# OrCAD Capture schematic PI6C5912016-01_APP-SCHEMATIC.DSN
size B; title: PI6C5912016-01 Application Schematic; rev: 1.0; note: Diodes Inc. Clock IC Application Engineering
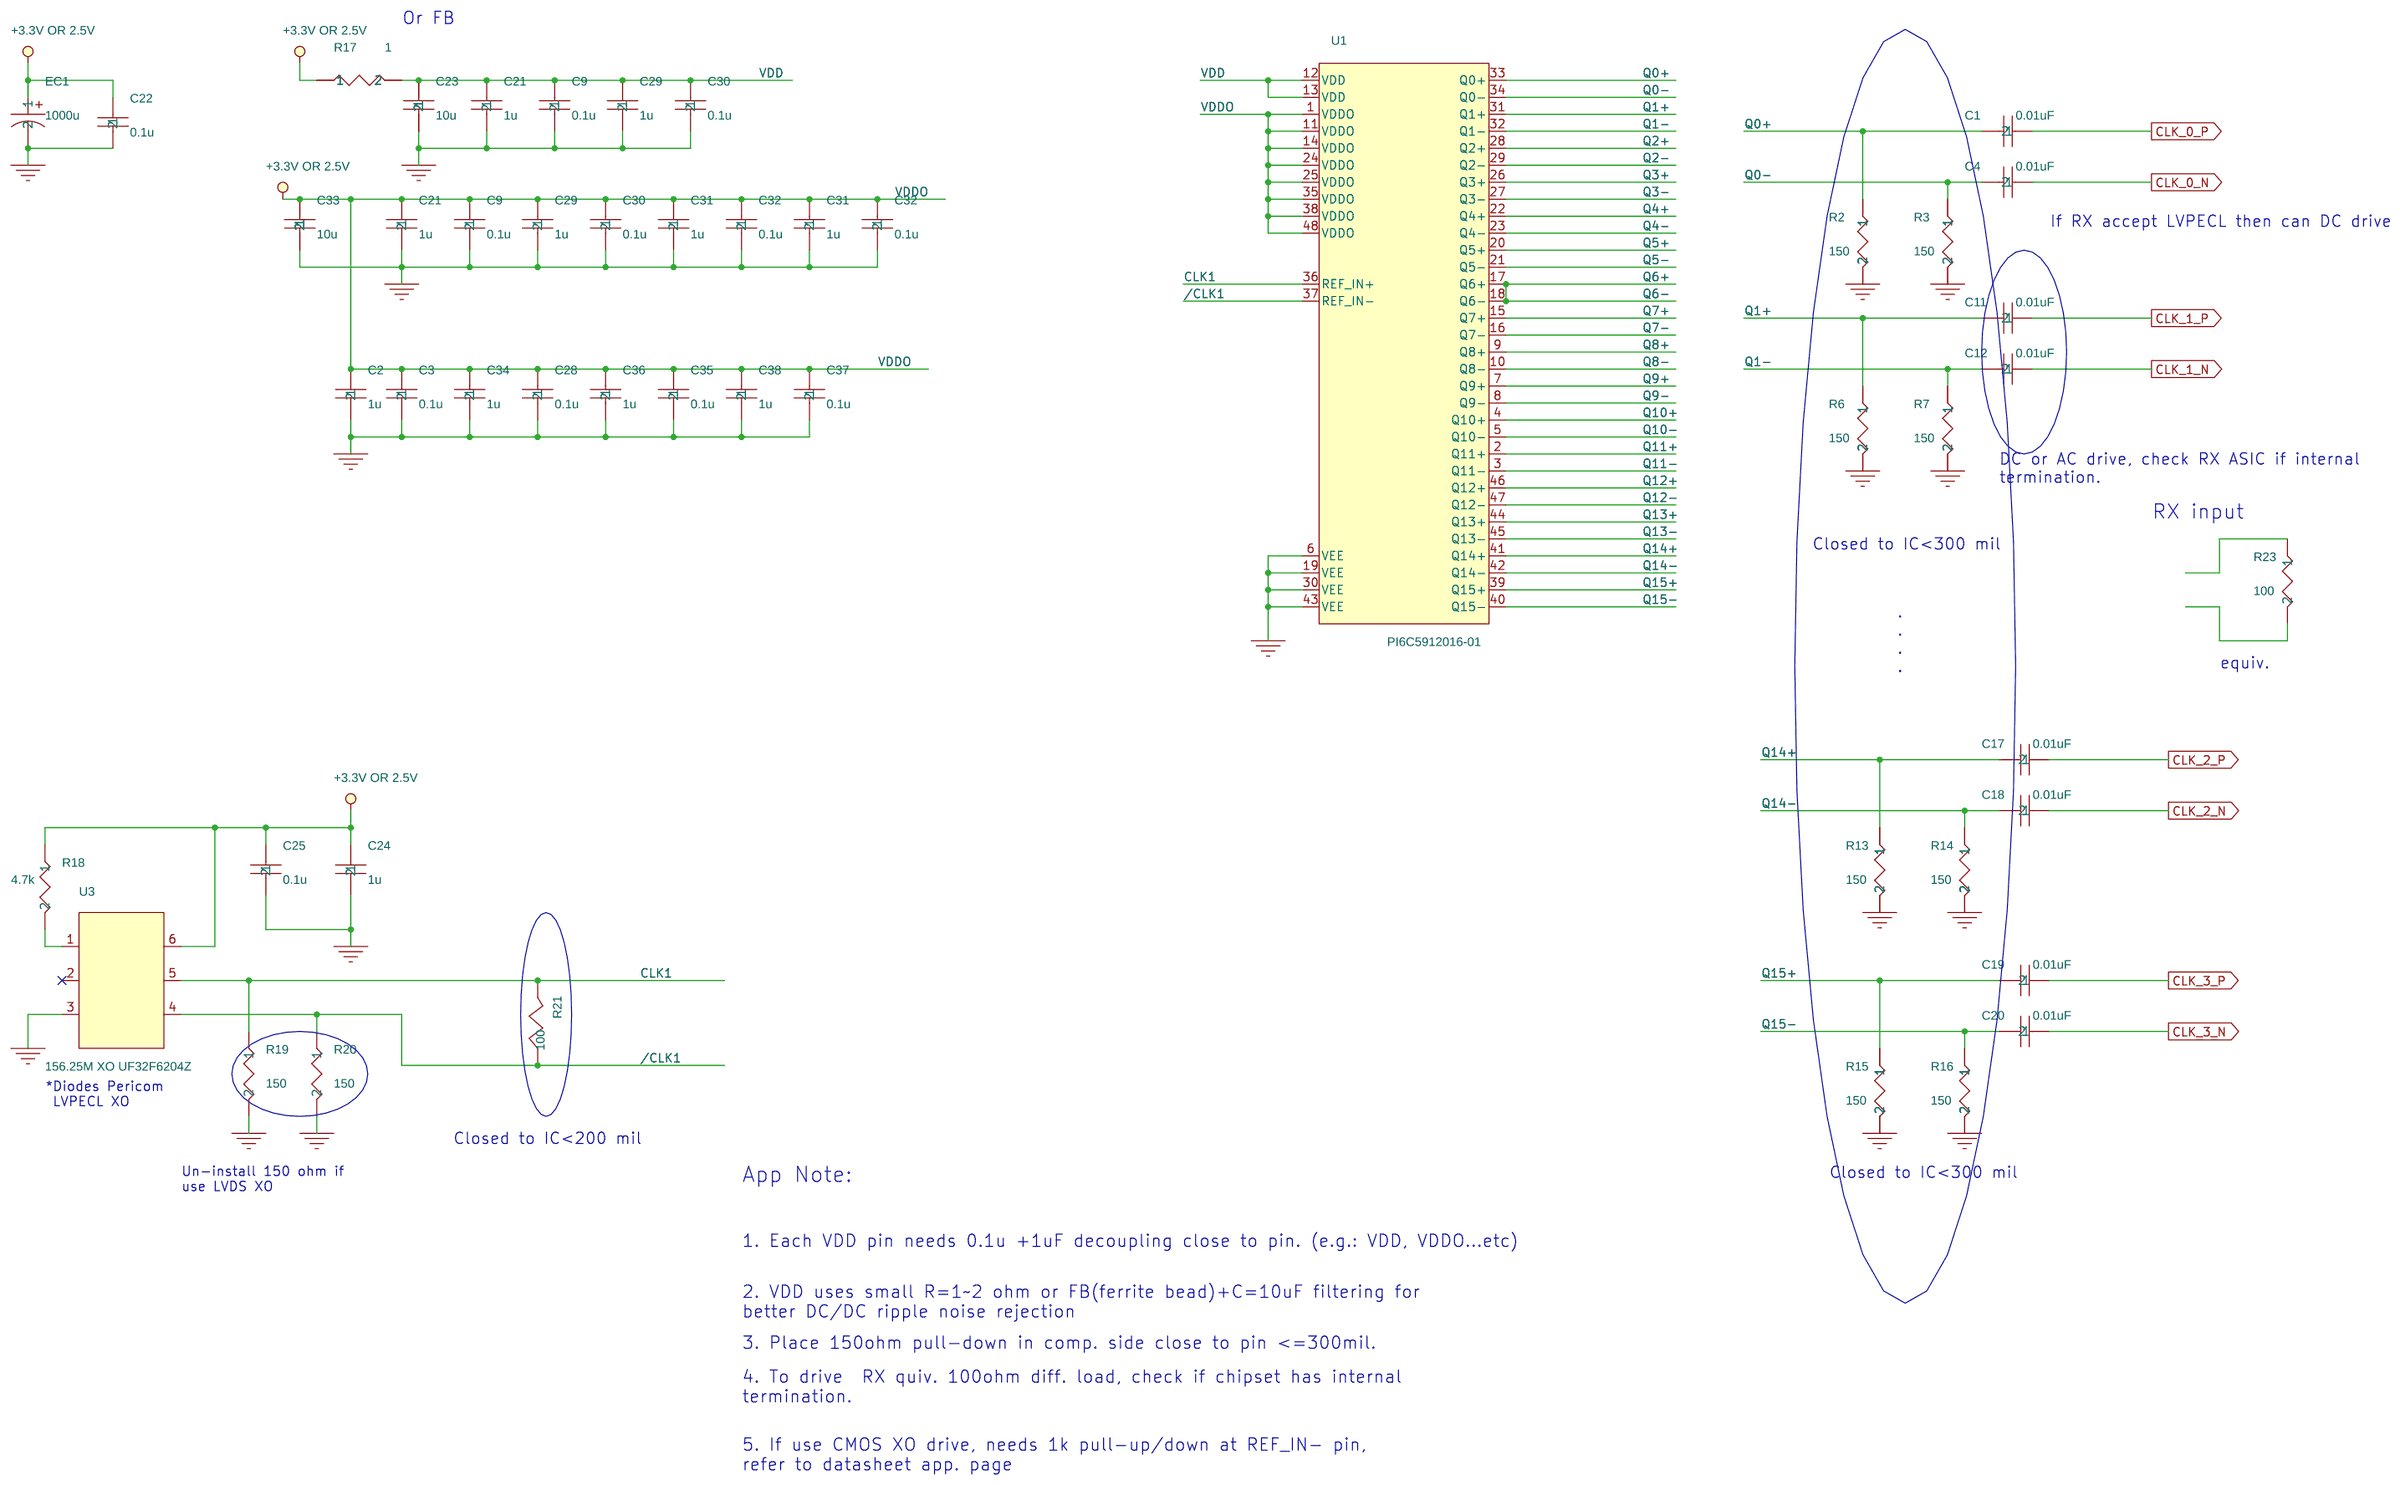
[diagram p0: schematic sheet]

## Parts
C1  0.01uF  [CC_0402]
C2  1u  [CC_0402]
C3  0.1u  [CC_0402]
C4  0.01uF  [CC_0402]
C9  0.1u  [CC_0402]
C9#2  0.1u  [CC_0402]
C11  0.01uF  [CC_0402]
C12  0.01uF  [CC_0402]
C17  0.01uF  [CC_0402]
C18  0.01uF  [CC_0402]
C19  0.01uF  [CC_0402]
C20  0.01uF  [CC_0402]
C21  1u  [CC_0805]
C21#2  1u  [CC_0805]
C22  0.1u  [CC_0402]
C23  10u  [CC_0805]
C24  1u  [CC_0402]
C25  0.1u  [CC_0402]
C28  0.1u  [CC_0402]
C29  1u  [CC_0805]
C29#2  1u  [CC_0805]
C30  0.1u  [CC_0402]
C30#2  0.1u  [CC_0402]
C31  1u  [CC_0805]
C31#2  1u  [CC_0805]
C32  0.1u  [CC_0402]
C32#2  0.1u  [CC_0402]
C33  10u  [CC_0805]
C34  1u  [CC_0402]
C35  0.1u  [CC_0402]
C36  1u  [CC_0402]
C37  0.1u  [CC_0402]
C38  1u  [CC_0402]
EC1  1000u  [CAP1000UF]
R2  150  [R_0402]
R3  150  [R_0402]
R6  150  [R_0402]
R7  150  [R_0402]
R13  150  [R_0402]
R14  150  [R_0402]
R15  150  [R_0402]
R16  150  [R_0402]
R17  1  [R_0402]
R18  4.7k  [R_0402]
R19  150  [R_0402]
R20  150  [R_0402]
R21  100
R23  100  [R_0402]
U1  PI6C5912016-01
U3  156.25M XO UF32F6204Z  [XO 5X7]

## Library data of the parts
C1 = C_10n_0402
C2 = C_0.1u_0402_1
C3 = C_0.1u_0402_8
C4 = C_10n_0402_3
C9 = C_0.1u_0402_12
C9#2 C30#2 C32#2 C38 = C_0.1u_0402
C11 = C_10n_0402_4
C12 = C_10n_0402_2
C17 = C_10n_0402_6
C18 = C_10n_0402_5
C19 = C_10n_0402_7
C20 = C_10n_0402_1
C21 = C_1.0u_0805_4
C21#2 C23 C29#2 C31#2 = C_1.0u_0805
C22 = C_0.1u_0402_6
C24 = C_0.1u_0402_15
C25 = C_0.1u_0402_14
C28 = C_0.1u_0402_9
C29 = C_1.0u_0805_5
C30 = C_0.1u_0402_7
C31 = C_1.0u_0805_7
C32 = C_0.1u_0402_4
C33 = C_1.0u_0805_1
C34 = C_0.1u_0402_5
C35 = C_0.1u_0402_2
C36 = C_0.1u_0402_16
C37 = C_0.1u_0402_3
EC1 = C_alum_1000u
R2 = R_0_2
R3 = R_0_8
R6 = R_0_3
R7 = R_0_7
R13 = R_0_6
R14 = R_0_4
R15 = R_0_5
R16 = R_0
R17 = R_0402
R18 = R_0402_3
R19 = R_0402_2
R20 = R_0402_1
R21 = res1
R23 = R_0_1
U1 = PI6C4911504-03_8
U3 = XO_5X7

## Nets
+3.3V or 2.5V: C2.1 C3.1 C9.1 C21.1 C22.1 C24.1 C25.1 C28.1 C29.1 C30.1 C31.1 C31#2.1 C32.1 C32#2.1 C33.1 C34.1 C35.1 C36.1 C37.1 C38.1 EC1.1 R17.1 R18.1 U1.1(VDDO) U1.11(VDDO) U1.14(VDDO) U1.24(VDDO) U1.25(VDDO) U1.35(VDDO) U1.38(VDDO) U1.48(VDDO) U3.6
GND: C2.2 C3.2 C9.2 C9#2.2 C21.2 C21#2.2 C22.2 C23.2 C24.2 C25.2 C28.2 C29.2 C29#2.2 C30.2 C30#2.2 C31.2 C31#2.2 C32.2 C32#2.2 C33.2 C34.2 C35.2 C36.2 C37.2 C38.2 EC1.2 R2.2 R3.2 R6.2 R7.2 R13.2 R14.2 R15.2 R16.2 R19.2 R20.2 U1.6(VEE) U1.19(VEE) U1.30(VEE) U1.43(VEE) U3.3
VDD: C9#2.1 C21#2.1 C23.1 C29#2.1 C30#2.1 R17.2 U1.12(VDD) U1.13(VDD)
/CLK1: R20.1 R21.1 U1.37(REF_IN-) U3.4
CLK1: R19.1 R21.2 U1.36(REF_IN+) U3.5
CLK_0_N: C4.1
CLK_0_P: C1.1
CLK_1_N: C12.1
CLK_1_P: C11.1
CLK_2_N: C18.1
CLK_2_P: C17.1
CLK_3_N: C20.1
CLK_3_P: C19.1
Q0+: C1.2 R2.1 U1.33(Q0+)
Q0-: C4.2 R3.1 U1.34(Q0-)
Q1+: C11.2 R6.1 U1.31(Q1+)
Q1-: C12.2 R7.1 U1.32(Q1-)
Q2+: U1.28(Q2+)
Q2-: U1.29(Q2-)
Q3+: U1.26(Q3+)
Q3-: U1.27(Q3-)
Q4+: U1.22(Q4+)
Q4-: U1.23(Q4-)
Q5+: U1.20(Q5+)
Q5-: U1.21(Q5-)
Q6+: U1.17(Q6+) U1.18(Q6-)
Q7+: U1.15(Q7+)
Q7-: U1.16(Q7-)
Q8+: U1.9(Q8+)
Q8-: U1.10(Q8-)
Q9+: U1.7(Q9+)
Q9-: U1.8(Q9-)
Q10+: U1.4(Q10+)
Q10-: U1.5(Q10-)
Q11+: U1.2(Q11+)
Q11-: U1.3(Q11-)
Q12+: U1.46(Q12+)
Q12-: U1.47(Q12-)
Q13+: U1.44(Q13+)
Q13-: U1.45(Q13-)
Q14+: C17.2 R13.1 U1.41(Q14+)
Q14-: C18.2 R14.1 U1.42(Q14-)
Q15+: C19.2 R15.1 U1.39(Q15+)
Q15-: C20.2 R16.1 U1.40(Q15-)
N4609914: R18.2 U3.1

Not connected (* = marked no-connect by the designer): R23 1 2; U3 2*

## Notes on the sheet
- Or FB
- If RX accept LVPECL then can DC drive
- DC or AC drive, check RX ASIC if internal
  termination.
- RX input
- Closed to IC<300 mil
- .
  .
  .
  .
- equiv.
- *Diodes Pericom
   LVPECL XO
- Closed to IC<200 mil
- Un-install 150 ohm if
  use LVDS XO
- App Note:
- Closed to IC<300 mil
- 1. Each VDD pin needs 0.1u +1uF decoupling close to pin. (e.g.: VDD, VDDO...etc)
- 2. VDD uses small R=1~2 ohm or FB(ferrite bead)+C=10uF filtering for
  better DC/DC ripple noise rejection
- 3. Place 150ohm pull-down in comp. side close to pin <=300mil.
- 4. To drive  RX quiv. 100ohm diff. load, check if chipset has internal
  termination.
- 5. If use CMOS XO drive, needs 1k pull-up/down at REF_IN- pin,
  refer to datasheet app. page
